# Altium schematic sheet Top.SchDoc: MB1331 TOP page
size A3; Date: Not used; ApprovedBy: Not used; CheckedBy: Not used; Author: Not used; CompanyName: STMicroelectronics; DrawnBy: Not used; Engineer: Not used; Organization: Not used; Address1: Not used; Address2: Not used; Address3: Not used; Address4: Not used; DocumentNumber: Not used; Revision: Not used; SheetNumber: 2; SheetTotal: 23
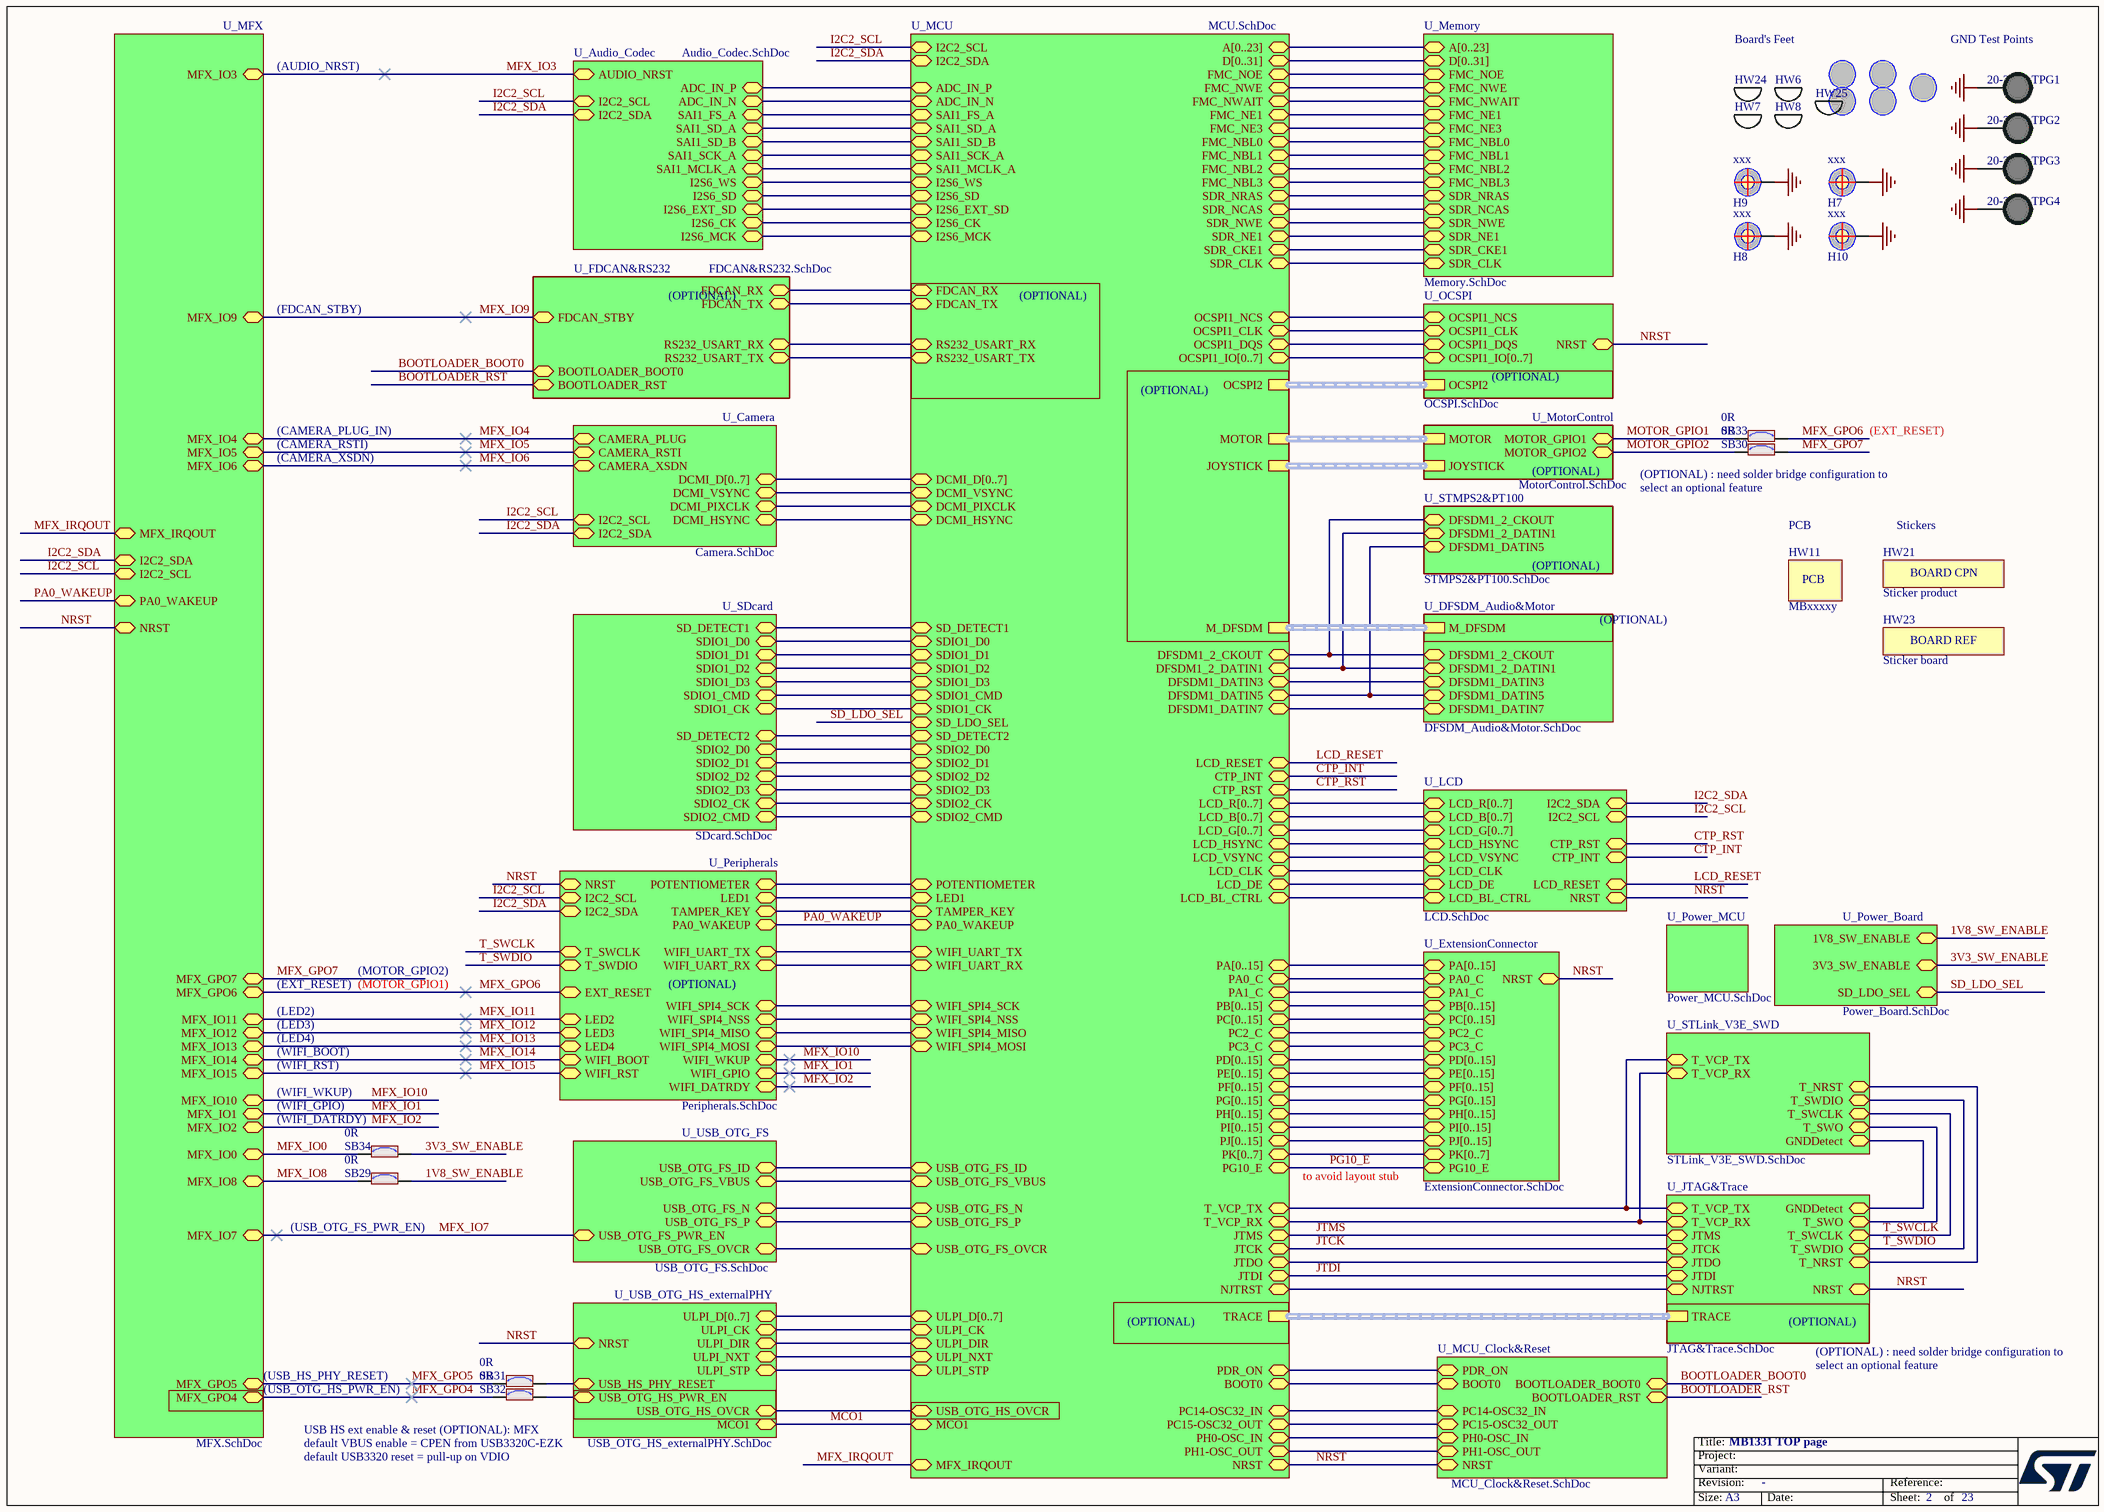
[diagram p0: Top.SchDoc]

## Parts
H7  value xxx  [PTH_M1261-3005-N_3P5X6_M3_H14]  (hidden comment: POSITION HOLE)  (no BOM)
H8  value xxx  [PTH_M1261-3005-N_3P5X6_M3_H14]  (hidden comment: POSITION HOLE)  (no BOM)
H9  value xxx  [PTH_M1261-3005-N_3P5X6_M3_H14]  (hidden comment: POSITION HOLE)  (no BOM)
H10  value xxx  [PTH_M1261-3005-N_3P5X6_M3_H14]  (hidden comment: POSITION HOLE)  (no BOM)
HW6  RUBBER_FOOT  (value not drawn)  (mechanical)
HW7  RUBBER_FOOT  (value not drawn)  (mechanical)
HW8  RUBBER_FOOT  (value not drawn)  (mechanical)
HW11  value MBxxxxy  (hidden comment: PCB)  (no BOM)
HW21  value Sticker product  [STICKER_25X9]  (hidden comment: STICKER_BOARD_CPN)  (no BOM)
HW23  value Sticker board  [STICKER_25X9]  (hidden comment: STICKER_BOARD_REF)  (no BOM)
HW24  RUBBER_FOOT  (value not drawn)  (mechanical)
HW25  RUBBER_FOOT  (value not drawn)  (mechanical)
SB29  value 0R  [SOLDER-BRIDGE_R0603-0R]  (hidden comment: SB_ON)
SB30  value 0R  [SOLDER-BRIDGE_R0603-0R]  (hidden comment: SB_ON)
SB31  value 0R  [SOLDER-BRIDGE_R0603-0R]  (hidden comment: SB_ON)
SB32  value 0R  [SOLDER-BRIDGE_R0603-0R]  (hidden comment: SB_ON)
SB33  value 0R  [SOLDER-BRIDGE_R0603-0R]  (hidden comment: SB_ON)
SB34  value 0R  [SOLDER-BRIDGE_R0603-0R]  (hidden comment: SB_ON)
TPG1  value 20-2137  [TP_PTH-1P02MM_TEST-TERMINAL_RS_101-2391_BLACK]  (hidden comment: Test_pin_conn_black)
TPG2  value 20-2137  [TP_PTH-1P02MM_TEST-TERMINAL_RS_101-2391_BLACK]  (hidden comment: Test_pin_conn_black)
TPG3  value 20-2137  [TP_PTH-1P02MM_TEST-TERMINAL_RS_101-2391_BLACK]  (hidden comment: Test_pin_conn_black)
TPG4  value 20-2137  [TP_PTH-1P02MM_TEST-TERMINAL_RS_101-2391_BLACK]  (hidden comment: Test_pin_conn_black)

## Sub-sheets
U_Audio_Codec = Audio_Codec.SchDoc: AUDIO_NRST (bidir), SAI1_SD_A (bidir), SAI1_SD_B (bidir), I2C2_SCL (bidir), I2C2_SDA (bidir), I2S6_WS (bidir), I2S6_EXT_SD (bidir), SAI1_FS_A (bidir), SAI1_SCK_A (bidir), SAI1_MCLK_A (bidir), ADC_IN_N (bidir), ADC_IN_P (bidir), I2S6_MCK (bidir), I2S6_CK (bidir), I2S6_SD (bidir)
U_Camera = Camera.SchDoc: CAMERA_RSTI (bidir), CAMERA_XSDN (bidir), DCMI_D[0..7] (bidir), CAMERA_PLUG (bidir), DCMI_HSYNC (bidir), DCMI_PIXCLK (bidir), DCMI_VSYNC (bidir), I2C2_SCL (bidir), I2C2_SDA (bidir)
U_DFSDM_Audio&Motor = DFSDM_Audio&Motor.SchDoc: DFSDM1_DATIN7 (bidir), DFSDM1_2_CKOUT (bidir), DFSDM1_2_DATIN1 (bidir), DFSDM1_DATIN3 (bidir), DFSDM1_DATIN5 (bidir), M_DFSDM (harness M_DFSDM)
U_ExtensionConnector = ExtensionConnector.SchDoc: PA[0..15] (bidir), PB[0..15] (bidir), PC[0..15] (bidir), PD[0..15] (bidir), PE[0..15] (bidir), PF[0..15] (bidir), PG[0..15] (bidir), PH[0..15] (bidir), PI[0..15] (bidir), PJ[0..15] (bidir), PK[0..7] (bidir), NRST (bidir), PA0_C (bidir), PA1_C (bidir), PC2_C (bidir), PC3_C (bidir), PG10_E (bidir)
U_FDCAN&RS232 = FDCAN&RS232.SchDoc: RS232_USART_TX (bidir), RS232_USART_RX (bidir), BOOTLOADER_BOOT0 (bidir), BOOTLOADER_RST (bidir), FDCAN_RX (bidir), FDCAN_TX (bidir), FDCAN_STBY (bidir)
U_JTAG&Trace = JTAG&Trace.SchDoc: JTMS (bidir), JTCK (bidir), JTDI (bidir), JTDO (bidir), NJTRST (bidir), NRST (bidir), TRACE (harness TRACE), T_VCP_TX (bidir), T_VCP_RX (bidir), GNDDetect (bidir), T_SWCLK (bidir), T_SWO (bidir), T_SWDIO (bidir), T_NRST (bidir)
U_LCD = LCD.SchDoc: LCD_R[0..7] (bidir), I2C2_SDA (bidir), I2C2_SCL (bidir), LCD_B[0..7] (bidir), LCD_G[0..7] (bidir), NRST (bidir), LCD_HSYNC (bidir), LCD_VSYNC (bidir), LCD_CLK (bidir), LCD_DE (bidir), CTP_INT (bidir), LCD_BL_CTRL (bidir), CTP_RST (bidir), LCD_RESET (bidir)
U_MCU = MCU.SchDoc: OCSPI1_NCS (bidir), SDR_CLK (bidir), FMC_NE3 (bidir), SDR_NCAS (bidir), SDR_NWE (bidir), SDR_NE1 (bidir), SDR_CKE1 (bidir), PH0-OSC_IN (bidir), NRST (bidir), BOOT0 (bidir), PDR_ON (bidir), FMC_NBL2 (bidir), FMC_NBL3 (bidir), LCD_HSYNC (bidir), LCD_VSYNC (bidir), LCD_CLK (bidir), PA0_WAKEUP (bidir), MCO1 (bidir), USB_OTG_FS_VBUS (bidir), USB_OTG_FS_ID (bidir), USB_OTG_FS_N (bidir), USB_OTG_FS_P (bidir), OCSPI1_CLK (bidir), T_VCP_TX (bidir), T_VCP_RX (bidir), OCSPI1_DQS (bidir), SDIO1_D0 (bidir), SDIO1_D1 (bidir), SDIO1_D2 (bidir), SDIO1_D3 (bidir), SDIO1_CK (bidir), TAMPER_KEY (bidir), PC14-OSC32_IN (bidir), PC15-OSC32_OUT (bidir), SDIO1_CMD (bidir), FMC_NOE (bidir), FMC_NWE (bidir), FMC_NWAIT (bidir), FMC_NE1 (bidir), FMC_NBL0 (bidir), FMC_NBL1 (bidir), SDR_NRAS (bidir), DFSDM1_DATIN7 (bidir), DFSDM1_2_CKOUT (bidir), DCMI_HSYNC (bidir), DCMI_PIXCLK (bidir), DCMI_VSYNC (bidir), FDCAN_RX (bidir), FDCAN_TX (bidir), PA[0..15] (bidir), PB[0..15] (bidir), PC[0..15] (bidir), PD[0..15] (bidir), PE[0..15] (bidir), PF[0..15] (bidir), PG[0..15] (bidir), PH[0..15] (bidir), PI[0..15] (bidir), PJ[0..15] (bidir), PK[0..7] (bidir), LCD_G[0..7] (bidir), LCD_B[0..7] (bidir), D[0..31] (bidir), A[0..23] (bidir), ULPI_D[0..7] (bidir), LCD_R[0..7] (bidir), LCD_DE (bidir), DFSDM1_2_DATIN1 (bidir), I2C2_SCL (bidir), I2C2_SDA (bidir), DCMI_D[0..7] (bidir), POTENTIOMETER (bidir), ULPI_NXT (bidir), ULPI_DIR (bidir), ULPI_STP (bidir), ULPI_CK (bidir), CTP_INT (bidir), CTP_RST (bidir), LCD_BL_CTRL (bidir), OCSPI1_IO[0..7] (bidir), PA0_C (bidir), PA1_C (bidir), PC2_C (bidir), PC3_C (bidir), JTMS (bidir), JTCK (bidir), JTDI (bidir), JTDO (bidir), NJTRST (bidir), DFSDM1_DATIN3 (bidir), DFSDM1_DATIN5 (bidir), LCD_RESET (bidir), MFX_IRQOUT (bidir), RS232_USART_TX (bidir), RS232_USART_RX (bidir), SDIO2_CK (bidir), SDIO2_D2 (bidir), SDIO2_D1 (bidir), SDIO2_D3 (bidir), SDIO2_D0 (bidir), SDIO2_CMD (bidir), JOYSTICK (harness JOYSTICK), MOTOR (harness MOTOR), OCSPI2 (harness OCSPI2), TRACE (harness TRACE), M_DFSDM (harness M_DFSDM), PH1-OSC_OUT (bidir), WIFI_SPI4_SCK (bidir), WIFI_SPI4_NSS (bidir), WIFI_SPI4_MISO (bidir), WIFI_SPI4_MOSI (bidir), USB_OTG_FS_OVCR (bidir), LED1 (bidir), ADC_IN_N (bidir), ADC_IN_P (bidir), USB_OTG_HS_OVCR (bidir), SD_DETECT1 (bidir), SD_DETECT2 (bidir), SD_LDO_SEL (bidir), SAI1_SD_A (bidir), SAI1_SD_B (bidir), I2S6_WS (bidir), I2S6_EXT_SD (bidir), SAI1_FS_A (bidir), SAI1_SCK_A (bidir), SAI1_MCLK_A (bidir), I2S6_MCK (bidir), I2S6_CK (bidir), I2S6_SD (bidir), PG10_E (bidir), WIFI_UART_TX (bidir), WIFI_UART_RX (bidir)
U_MCU_Clock&Reset = MCU_Clock&Reset.SchDoc: BOOTLOADER_BOOT0 (bidir), BOOTLOADER_RST (bidir), NRST (bidir), BOOT0 (bidir), PDR_ON (bidir), PH0-OSC_IN (bidir), PC14-OSC32_IN (bidir), PC15-OSC32_OUT (bidir), PH1-OSC_OUT (bidir)
U_Memory = Memory.SchDoc: FMC_NE1 (bidir), FMC_NWE (bidir), FMC_NOE (bidir), FMC_NWAIT (bidir), FMC_NBL0 (bidir), FMC_NBL1 (bidir), D[0..31] (bidir), A[0..23] (bidir), SDR_NCAS (bidir), SDR_NWE (bidir), SDR_NRAS (bidir), SDR_NE1 (bidir), SDR_CKE1 (bidir), SDR_CLK (bidir), FMC_NBL3 (bidir), FMC_NBL2 (bidir), FMC_NE3 (bidir)
U_MFX = MFX.SchDoc: MFX_IRQOUT (bidir), I2C2_SDA (bidir), I2C2_SCL (bidir), PA0_WAKEUP (bidir), NRST (bidir), MFX_IO9 (bidir), MFX_IO4 (bidir), MFX_IO5 (bidir), MFX_IO6 (bidir), MFX_IO8 (bidir), MFX_IO3 (bidir), MFX_IO7 (bidir), MFX_IO14 (bidir), MFX_IO15 (bidir), MFX_IO12 (bidir), MFX_IO11 (bidir), MFX_IO13 (bidir), MFX_GPO5 (bidir), MFX_GPO4 (bidir), MFX_IO0 (bidir), MFX_GPO6 (bidir), MFX_GPO7 (bidir), MFX_IO1 (bidir), MFX_IO2 (bidir), MFX_IO10 (bidir)
U_MotorControl = MotorControl.SchDoc: MOTOR (harness MOTOR), JOYSTICK (harness JOYSTICK), MOTOR_GPIO1 (bidir), MOTOR_GPIO2 (bidir)
U_OCSPI = OCSPI.SchDoc: NRST (bidir), OCSPI1_NCS (bidir), OCSPI1_DQS (bidir), OCSPI1_CLK (bidir), OCSPI1_IO[0..7] (bidir), OCSPI2 (harness OCSPI2)
U_Peripherals = Peripherals.SchDoc: POTENTIOMETER (bidir), LED1 (bidir), LED2 (bidir), LED3 (bidir), LED4 (bidir), WIFI_UART_RX (bidir), WIFI_UART_TX (bidir), WIFI_RST (bidir), EXT_RESET (bidir), TAMPER_KEY (bidir), NRST (bidir), PA0_WAKEUP (bidir), I2C2_SCL (bidir), I2C2_SDA (bidir), WIFI_BOOT (bidir), WIFI_SPI4_SCK (bidir), WIFI_SPI4_NSS (bidir), WIFI_SPI4_MISO (bidir), WIFI_SPI4_MOSI (bidir), T_SWCLK (bidir), T_SWDIO (bidir), WIFI_WKUP (bidir), WIFI_GPIO (bidir), WIFI_DATRDY (bidir)
U_Power_Board = Power_Board.SchDoc: 1V8_SW_ENABLE (bidir), 3V3_SW_ENABLE (bidir), SD_LDO_SEL (bidir)
U_Power_MCU = Power_MCU.SchDoc: no entries
U_SDcard = SDcard.SchDoc: SDIO1_D0 (bidir), SDIO1_D1 (bidir), SDIO1_D2 (bidir), SDIO1_D3 (bidir), SDIO1_CMD (bidir), SD_DETECT2 (bidir), SDIO1_CK (bidir), SDIO2_CK (bidir), SDIO2_D2 (bidir), SDIO2_D1 (bidir), SDIO2_D3 (bidir), SDIO2_D0 (bidir), SDIO2_CMD (bidir), SD_DETECT1 (bidir)
U_STLink_V3E_SWD = STLink_V3E_SWD.SchDoc: T_SWCLK (bidir), T_SWO (bidir), T_SWDIO (bidir), T_VCP_TX (bidir), T_VCP_RX (bidir), GNDDetect (bidir), T_NRST (bidir)
U_STMPS2&PT100 = STMPS2&PT100.SchDoc: DFSDM1_2_CKOUT (bidir), DFSDM1_2_DATIN1 (bidir), DFSDM1_DATIN5 (bidir)
U_USB_OTG_FS = USB_OTG_FS.SchDoc: USB_OTG_FS_VBUS (bidir), USB_OTG_FS_N (bidir), USB_OTG_FS_P (bidir), USB_OTG_FS_ID (bidir), USB_OTG_FS_PWR_EN (bidir), USB_OTG_FS_OVCR (bidir)
U_USB_OTG_HS_externalPHY = USB_OTG_HS_externalPHY.SchDoc: ULPI_D[0..7] (bidir), ULPI_CK (bidir), ULPI_DIR (bidir), ULPI_NXT (bidir), ULPI_STP (bidir), USB_HS_PHY_RESET (bidir), NRST (bidir), USB_OTG_HS_PWR_EN (bidir), USB_OTG_HS_OVCR (bidir), MCO1 (bidir)

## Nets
GND: H7.1 H8.1 H9.1 H10.1 TPG1.1 TPG2.1 TPG3.1 TPG4.1
1V8_SW_ENABLE: SB29.1 ; sheet U_Power_Board/1V8_SW_ENABLE
3V3_SW_ENABLE: SB34.1 ; sheet U_Power_Board/3V3_SW_ENABLE
BOOTLOADER_BOOT0: sheet U_MCU_Clock&Reset/BOOTLOADER_BOOT0, sheet U_FDCAN&RS232/BOOTLOADER_BOOT0
BOOTLOADER_RST: sheet U_MCU_Clock&Reset/BOOTLOADER_RST, sheet U_FDCAN&RS232/BOOTLOADER_RST
CTP_INT: sheet U_MCU/CTP_INT, sheet U_LCD/CTP_INT
CTP_RST: sheet U_MCU/CTP_RST, sheet U_LCD/CTP_RST
I2C2_SCL: sheet U_Camera/I2C2_SCL, sheet U_MCU/I2C2_SCL, sheet U_Audio_Codec/I2C2_SCL, sheet U_LCD/I2C2_SCL, sheet U_MFX/I2C2_SCL, sheet U_Peripherals/I2C2_SCL
I2C2_SDA: sheet U_Camera/I2C2_SDA, sheet U_MCU/I2C2_SDA, sheet U_Audio_Codec/I2C2_SDA, sheet U_LCD/I2C2_SDA, sheet U_MFX/I2C2_SDA, sheet U_Peripherals/I2C2_SDA
JTCK: sheet U_MCU/JTCK, sheet U_JTAG&Trace/JTCK
JTDI: sheet U_MCU/JTDI, sheet U_JTAG&Trace/JTDI
JTMS: sheet U_MCU/JTMS, sheet U_JTAG&Trace/JTMS
LCD_RESET: sheet U_MCU/LCD_RESET, sheet U_LCD/LCD_RESET
MCO1: sheet U_MCU/MCO1, sheet U_USB_OTG_HS_externalPHY/MCO1
MFX_GPO4: SB32.2 ; sheet U_MFX/MFX_GPO4
MFX_GPO5: SB31.2 ; sheet U_MFX/MFX_GPO5
MFX_GPO6: SB33.1 ; sheet U_MFX/MFX_GPO6, sheet U_Peripherals/EXT_RESET
MFX_GPO7: SB30.1 ; sheet U_MFX/MFX_GPO7
MFX_IO0: SB34.2 ; sheet U_MFX/MFX_IO0
MFX_IO1: sheet U_MFX/MFX_IO1, sheet U_Peripherals/WIFI_GPIO
MFX_IO2: sheet U_MFX/MFX_IO2, sheet U_Peripherals/WIFI_DATRDY
MFX_IO3: sheet U_Audio_Codec/AUDIO_NRST, sheet U_MFX/MFX_IO3
MFX_IO4: sheet U_Camera/CAMERA_PLUG, sheet U_MFX/MFX_IO4
MFX_IO5: sheet U_Camera/CAMERA_RSTI, sheet U_MFX/MFX_IO5
MFX_IO6: sheet U_Camera/CAMERA_XSDN, sheet U_MFX/MFX_IO6
MFX_IO7: sheet U_MFX/MFX_IO7, sheet U_USB_OTG_FS/USB_OTG_FS_PWR_EN
MFX_IO8: SB29.2 ; sheet U_MFX/MFX_IO8
MFX_IO9: sheet U_MFX/MFX_IO9, sheet U_FDCAN&RS232/FDCAN_STBY
MFX_IO10: sheet U_MFX/MFX_IO10, sheet U_Peripherals/WIFI_WKUP
MFX_IO11: sheet U_MFX/MFX_IO11, sheet U_Peripherals/LED2
MFX_IO12: sheet U_MFX/MFX_IO12, sheet U_Peripherals/LED3
MFX_IO13: sheet U_MFX/MFX_IO13, sheet U_Peripherals/LED4
MFX_IO14: sheet U_MFX/MFX_IO14, sheet U_Peripherals/WIFI_BOOT
MFX_IO15: sheet U_MFX/MFX_IO15, sheet U_Peripherals/WIFI_RST
MFX_IRQOUT: sheet U_MCU/MFX_IRQOUT, sheet U_MFX/MFX_IRQOUT
MOTOR_GPIO1: SB33.2 ; sheet U_MotorControl/MOTOR_GPIO1
MOTOR_GPIO2: SB30.2 ; sheet U_MotorControl/MOTOR_GPIO2
NRST: sheet U_MCU/NRST, sheet U_LCD/NRST, sheet U_JTAG&Trace/NRST, sheet U_MCU_Clock&Reset/NRST, sheet U_MFX/NRST, sheet U_OCSPI/NRST, sheet U_Peripherals/NRST, sheet U_ExtensionConnector/NRST, sheet U_USB_OTG_HS_externalPHY/NRST
PA0_WAKEUP: sheet U_MCU/PA0_WAKEUP, sheet U_MFX/PA0_WAKEUP, sheet U_Peripherals/PA0_WAKEUP
PG10_E: sheet U_MCU/PG10_E, sheet U_ExtensionConnector/PG10_E
SD_LDO_SEL: sheet U_MCU/SD_LDO_SEL, sheet U_Power_Board/SD_LDO_SEL
T_SWCLK: sheet U_JTAG&Trace/T_SWCLK, sheet U_Peripherals/T_SWCLK, sheet U_STLink_V3E_SWD/T_SWCLK
T_SWDIO: sheet U_JTAG&Trace/T_SWDIO, sheet U_Peripherals/T_SWDIO, sheet U_STLink_V3E_SWD/T_SWDIO
NetSB31_1: SB31.1 ; sheet U_USB_OTG_HS_externalPHY/USB_HS_PHY_RESET
NetSB32_1: SB32.1 ; sheet U_USB_OTG_HS_externalPHY/USB_OTG_HS_PWR_EN
(unnamed): sheet U_SDcard/SDIO1_D0, sheet U_MCU/SDIO1_D0
(unnamed): sheet U_SDcard/SDIO1_D1, sheet U_MCU/SDIO1_D1  [a separate net that carries the same name]
(unnamed): sheet U_SDcard/SDIO1_D2, sheet U_MCU/SDIO1_D2  [a separate net that carries the same name]
(unnamed): sheet U_SDcard/SDIO1_D3, sheet U_MCU/SDIO1_D3  [a separate net that carries the same name]
(unnamed): sheet U_SDcard/SDIO1_CMD, sheet U_MCU/SDIO1_CMD  [a separate net that carries the same name]
(unnamed): sheet U_SDcard/SD_DETECT2, sheet U_MCU/SD_DETECT2  [a separate net that carries the same name]
(unnamed): sheet U_SDcard/SDIO1_CK, sheet U_MCU/SDIO1_CK  [a separate net that carries the same name]
(unnamed): sheet U_SDcard/SDIO2_CK, sheet U_MCU/SDIO2_CK  [a separate net that carries the same name]
(unnamed): sheet U_SDcard/SDIO2_D2, sheet U_MCU/SDIO2_D2  [a separate net that carries the same name]
(unnamed): sheet U_SDcard/SDIO2_D1, sheet U_MCU/SDIO2_D1  [a separate net that carries the same name]
(unnamed): sheet U_SDcard/SDIO2_D3, sheet U_MCU/SDIO2_D3  [a separate net that carries the same name]
(unnamed): sheet U_SDcard/SDIO2_D0, sheet U_MCU/SDIO2_D0  [a separate net that carries the same name]
(unnamed): sheet U_SDcard/SDIO2_CMD, sheet U_MCU/SDIO2_CMD  [a separate net that carries the same name]
(unnamed): sheet U_SDcard/SD_DETECT1, sheet U_MCU/SD_DETECT1  [a separate net that carries the same name]
(unnamed): sheet U_Camera/DCMI_HSYNC, sheet U_MCU/DCMI_HSYNC  [a separate net that carries the same name]
(unnamed): sheet U_Camera/DCMI_PIXCLK, sheet U_MCU/DCMI_PIXCLK  [a separate net that carries the same name]
(unnamed): sheet U_Camera/DCMI_VSYNC, sheet U_MCU/DCMI_VSYNC  [a separate net that carries the same name]
(unnamed): sheet U_MCU/OCSPI1_NCS, sheet U_OCSPI/OCSPI1_NCS  [a separate net that carries the same name]
(unnamed): sheet U_MCU/SDR_CLK, sheet U_Memory/SDR_CLK  [a separate net that carries the same name]
(unnamed): sheet U_MCU/FMC_NE3, sheet U_Memory/FMC_NE3  [a separate net that carries the same name]
(unnamed): sheet U_MCU/SDR_NCAS, sheet U_Memory/SDR_NCAS  [a separate net that carries the same name]
(unnamed): sheet U_MCU/SDR_NWE, sheet U_Memory/SDR_NWE  [a separate net that carries the same name]
(unnamed): sheet U_MCU/SDR_NE1, sheet U_Memory/SDR_NE1  [a separate net that carries the same name]
(unnamed): sheet U_MCU/SDR_CKE1, sheet U_Memory/SDR_CKE1  [a separate net that carries the same name]
(unnamed): sheet U_MCU/PH0-OSC_IN, sheet U_MCU_Clock&Reset/PH0-OSC_IN  [a separate net that carries the same name]
(unnamed): sheet U_MCU/BOOT0, sheet U_MCU_Clock&Reset/BOOT0  [a separate net that carries the same name]
(unnamed): sheet U_MCU/PDR_ON, sheet U_MCU_Clock&Reset/PDR_ON  [a separate net that carries the same name]
(unnamed): sheet U_MCU/FMC_NBL2, sheet U_Memory/FMC_NBL2  [a separate net that carries the same name]
(unnamed): sheet U_MCU/FMC_NBL3, sheet U_Memory/FMC_NBL3  [a separate net that carries the same name]
(unnamed): sheet U_MCU/LCD_HSYNC, sheet U_LCD/LCD_HSYNC  [a separate net that carries the same name]
(unnamed): sheet U_MCU/LCD_VSYNC, sheet U_LCD/LCD_VSYNC  [a separate net that carries the same name]
(unnamed): sheet U_MCU/LCD_CLK, sheet U_LCD/LCD_CLK  [a separate net that carries the same name]
(unnamed): sheet U_MCU/USB_OTG_FS_VBUS, sheet U_USB_OTG_FS/USB_OTG_FS_VBUS  [a separate net that carries the same name]
(unnamed): sheet U_MCU/USB_OTG_FS_ID, sheet U_USB_OTG_FS/USB_OTG_FS_ID  [a separate net that carries the same name]
(unnamed): sheet U_MCU/USB_OTG_FS_N, sheet U_USB_OTG_FS/USB_OTG_FS_N  [a separate net that carries the same name]
(unnamed): sheet U_MCU/USB_OTG_FS_P, sheet U_USB_OTG_FS/USB_OTG_FS_P  [a separate net that carries the same name]
(unnamed): sheet U_MCU/OCSPI1_CLK, sheet U_OCSPI/OCSPI1_CLK  [a separate net that carries the same name]
(unnamed): sheet U_MCU/T_VCP_TX, sheet U_JTAG&Trace/T_VCP_TX, sheet U_STLink_V3E_SWD/T_VCP_TX  [a separate net that carries the same name]
(unnamed): sheet U_MCU/T_VCP_RX, sheet U_JTAG&Trace/T_VCP_RX, sheet U_STLink_V3E_SWD/T_VCP_RX  [a separate net that carries the same name]
(unnamed): sheet U_MCU/OCSPI1_DQS, sheet U_OCSPI/OCSPI1_DQS  [a separate net that carries the same name]
(unnamed): sheet U_MCU/TAMPER_KEY, sheet U_Peripherals/TAMPER_KEY  [a separate net that carries the same name]
(unnamed): sheet U_MCU/PC14-OSC32_IN, sheet U_MCU_Clock&Reset/PC14-OSC32_IN  [a separate net that carries the same name]
(unnamed): sheet U_MCU/PC15-OSC32_OUT, sheet U_MCU_Clock&Reset/PC15-OSC32_OUT  [a separate net that carries the same name]
(unnamed): sheet U_MCU/FMC_NOE, sheet U_Memory/FMC_NOE  [a separate net that carries the same name]
(unnamed): sheet U_MCU/FMC_NWE, sheet U_Memory/FMC_NWE  [a separate net that carries the same name]
(unnamed): sheet U_MCU/FMC_NWAIT, sheet U_Memory/FMC_NWAIT  [a separate net that carries the same name]
(unnamed): sheet U_MCU/FMC_NE1, sheet U_Memory/FMC_NE1  [a separate net that carries the same name]
(unnamed): sheet U_MCU/FMC_NBL0, sheet U_Memory/FMC_NBL0  [a separate net that carries the same name]
(unnamed): sheet U_MCU/FMC_NBL1, sheet U_Memory/FMC_NBL1  [a separate net that carries the same name]
(unnamed): sheet U_MCU/SDR_NRAS, sheet U_Memory/SDR_NRAS  [a separate net that carries the same name]
(unnamed): sheet U_MCU/DFSDM1_DATIN7, sheet U_DFSDM_Audio&Motor/DFSDM1_DATIN7  [a separate net that carries the same name]
(unnamed): sheet U_MCU/DFSDM1_2_CKOUT, sheet U_DFSDM_Audio&Motor/DFSDM1_2_CKOUT, sheet U_STMPS2&PT100/DFSDM1_2_CKOUT  [a separate net that carries the same name]
(unnamed): sheet U_MCU/FDCAN_RX, sheet U_FDCAN&RS232/FDCAN_RX  [a separate net that carries the same name]
(unnamed): sheet U_MCU/FDCAN_TX, sheet U_FDCAN&RS232/FDCAN_TX  [a separate net that carries the same name]
(unnamed): sheet U_MCU/LCD_DE, sheet U_LCD/LCD_DE  [a separate net that carries the same name]
(unnamed): sheet U_MCU/DFSDM1_2_DATIN1, sheet U_DFSDM_Audio&Motor/DFSDM1_2_DATIN1, sheet U_STMPS2&PT100/DFSDM1_2_DATIN1  [a separate net that carries the same name]
(unnamed): sheet U_MCU/POTENTIOMETER, sheet U_Peripherals/POTENTIOMETER  [a separate net that carries the same name]
(unnamed): sheet U_MCU/ULPI_NXT, sheet U_USB_OTG_HS_externalPHY/ULPI_NXT  [a separate net that carries the same name]
(unnamed): sheet U_MCU/ULPI_DIR, sheet U_USB_OTG_HS_externalPHY/ULPI_DIR  [a separate net that carries the same name]
(unnamed): sheet U_MCU/ULPI_STP, sheet U_USB_OTG_HS_externalPHY/ULPI_STP  [a separate net that carries the same name]
(unnamed): sheet U_MCU/ULPI_CK, sheet U_USB_OTG_HS_externalPHY/ULPI_CK  [a separate net that carries the same name]
(unnamed): sheet U_MCU/LCD_BL_CTRL, sheet U_LCD/LCD_BL_CTRL  [a separate net that carries the same name]
(unnamed): sheet U_MCU/PA0_C, sheet U_ExtensionConnector/PA0_C  [a separate net that carries the same name]
(unnamed): sheet U_MCU/PA1_C, sheet U_ExtensionConnector/PA1_C  [a separate net that carries the same name]
(unnamed): sheet U_MCU/PC2_C, sheet U_ExtensionConnector/PC2_C  [a separate net that carries the same name]
(unnamed): sheet U_MCU/PC3_C, sheet U_ExtensionConnector/PC3_C  [a separate net that carries the same name]
(unnamed): sheet U_MCU/JTDO, sheet U_JTAG&Trace/JTDO  [a separate net that carries the same name]
(unnamed): sheet U_MCU/NJTRST, sheet U_JTAG&Trace/NJTRST  [a separate net that carries the same name]
(unnamed): sheet U_MCU/DFSDM1_DATIN3, sheet U_DFSDM_Audio&Motor/DFSDM1_DATIN3  [a separate net that carries the same name]
(unnamed): sheet U_MCU/DFSDM1_DATIN5, sheet U_DFSDM_Audio&Motor/DFSDM1_DATIN5, sheet U_STMPS2&PT100/DFSDM1_DATIN5  [a separate net that carries the same name]
(unnamed): sheet U_MCU/RS232_USART_TX, sheet U_FDCAN&RS232/RS232_USART_TX  [a separate net that carries the same name]
(unnamed): sheet U_MCU/RS232_USART_RX, sheet U_FDCAN&RS232/RS232_USART_RX  [a separate net that carries the same name]
(unnamed): sheet U_MCU/PH1-OSC_OUT, sheet U_MCU_Clock&Reset/PH1-OSC_OUT  [a separate net that carries the same name]
(unnamed): sheet U_MCU/WIFI_SPI4_SCK, sheet U_Peripherals/WIFI_SPI4_SCK  [a separate net that carries the same name]
(unnamed): sheet U_MCU/WIFI_SPI4_NSS, sheet U_Peripherals/WIFI_SPI4_NSS  [a separate net that carries the same name]
(unnamed): sheet U_MCU/WIFI_SPI4_MISO, sheet U_Peripherals/WIFI_SPI4_MISO  [a separate net that carries the same name]
(unnamed): sheet U_MCU/WIFI_SPI4_MOSI, sheet U_Peripherals/WIFI_SPI4_MOSI  [a separate net that carries the same name]
(unnamed): sheet U_MCU/USB_OTG_FS_OVCR, sheet U_USB_OTG_FS/USB_OTG_FS_OVCR  [a separate net that carries the same name]
(unnamed): sheet U_MCU/LED1, sheet U_Peripherals/LED1  [a separate net that carries the same name]
(unnamed): sheet U_MCU/ADC_IN_N, sheet U_Audio_Codec/ADC_IN_N  [a separate net that carries the same name]
(unnamed): sheet U_MCU/ADC_IN_P, sheet U_Audio_Codec/ADC_IN_P  [a separate net that carries the same name]
(unnamed): sheet U_MCU/USB_OTG_HS_OVCR, sheet U_USB_OTG_HS_externalPHY/USB_OTG_HS_OVCR  [a separate net that carries the same name]
(unnamed): sheet U_MCU/SAI1_SD_A, sheet U_Audio_Codec/SAI1_SD_A  [a separate net that carries the same name]
(unnamed): sheet U_MCU/SAI1_SD_B, sheet U_Audio_Codec/SAI1_SD_B  [a separate net that carries the same name]
(unnamed): sheet U_MCU/I2S6_WS, sheet U_Audio_Codec/I2S6_WS  [a separate net that carries the same name]
(unnamed): sheet U_MCU/I2S6_EXT_SD, sheet U_Audio_Codec/I2S6_EXT_SD  [a separate net that carries the same name]
(unnamed): sheet U_MCU/SAI1_FS_A, sheet U_Audio_Codec/SAI1_FS_A  [a separate net that carries the same name]
(unnamed): sheet U_MCU/SAI1_SCK_A, sheet U_Audio_Codec/SAI1_SCK_A  [a separate net that carries the same name]
(unnamed): sheet U_MCU/SAI1_MCLK_A, sheet U_Audio_Codec/SAI1_MCLK_A  [a separate net that carries the same name]
(unnamed): sheet U_MCU/I2S6_MCK, sheet U_Audio_Codec/I2S6_MCK  [a separate net that carries the same name]
(unnamed): sheet U_MCU/I2S6_CK, sheet U_Audio_Codec/I2S6_CK  [a separate net that carries the same name]
(unnamed): sheet U_MCU/I2S6_SD, sheet U_Audio_Codec/I2S6_SD  [a separate net that carries the same name]
(unnamed): sheet U_MCU/WIFI_UART_TX, sheet U_Peripherals/WIFI_UART_TX  [a separate net that carries the same name]
(unnamed): sheet U_MCU/WIFI_UART_RX, sheet U_Peripherals/WIFI_UART_RX  [a separate net that carries the same name]
(unnamed): sheet U_JTAG&Trace/GNDDetect, sheet U_STLink_V3E_SWD/GNDDetect  [a separate net that carries the same name]
(unnamed): sheet U_JTAG&Trace/T_SWO, sheet U_STLink_V3E_SWD/T_SWO  [a separate net that carries the same name]
(unnamed): sheet U_JTAG&Trace/T_NRST, sheet U_STLink_V3E_SWD/T_NRST  [a separate net that carries the same name]

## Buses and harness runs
bus sheet U_Camera/DCMI_D[0..7] = sheet U_MCU/DCMI_D[0..7]
bus sheet U_ExtensionConnector/PA[0..15] = sheet U_MCU/PA[0..15]
bus sheet U_ExtensionConnector/PB[0..15] = sheet U_MCU/PB[0..15]
bus sheet U_ExtensionConnector/PC[0..15] = sheet U_MCU/PC[0..15]
bus sheet U_ExtensionConnector/PD[0..15] = sheet U_MCU/PD[0..15]
bus sheet U_ExtensionConnector/PE[0..15] = sheet U_MCU/PE[0..15]
bus sheet U_ExtensionConnector/PF[0..15] = sheet U_MCU/PF[0..15]
bus sheet U_ExtensionConnector/PG[0..15] = sheet U_MCU/PG[0..15]
bus sheet U_ExtensionConnector/PH[0..15] = sheet U_MCU/PH[0..15]
bus sheet U_ExtensionConnector/PI[0..15] = sheet U_MCU/PI[0..15]
bus sheet U_ExtensionConnector/PJ[0..15] = sheet U_MCU/PJ[0..15]
bus sheet U_ExtensionConnector/PK[0..7] = sheet U_MCU/PK[0..7]
bus sheet U_LCD/LCD_B[0..7] = sheet U_MCU/LCD_B[0..7]
bus sheet U_LCD/LCD_G[0..7] = sheet U_MCU/LCD_G[0..7]
bus sheet U_LCD/LCD_R[0..7] = sheet U_MCU/LCD_R[0..7]
bus sheet U_MCU/A[0..23] = sheet U_Memory/A[0..23]
bus sheet U_MCU/D[0..31] = sheet U_Memory/D[0..31]
bus sheet U_MCU/OCSPI1_IO[0..7] = sheet U_OCSPI/OCSPI1_IO[0..7]
bus sheet U_MCU/ULPI_D[0..7] = sheet U_USB_OTG_HS_externalPHY/ULPI_D[0..7]
harness sheet U_DFSDM_Audio&Motor/M_DFSDM = sheet U_MCU/M_DFSDM
harness sheet U_JTAG&Trace/TRACE = sheet U_MCU/TRACE
harness sheet U_MCU/JOYSTICK = sheet U_MotorControl/JOYSTICK
harness sheet U_MCU/MOTOR = sheet U_MotorControl/MOTOR
harness sheet U_MCU/OCSPI2 = sheet U_OCSPI/OCSPI2

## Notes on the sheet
- Board's Feet
- (near TPG1) GND Test Points
- (AUDIO_NRST)
- (FDCAN_STBY)
- (OPTIONAL)
- (CAMERA_PLUG_IN)
- (CAMERA_RSTI)
- (EXT_RESET)
- (CAMERA_XSDN)
- (near SB30) (OPTIONAL) : need solder bridge configuration to select an optional feature
- (near HW11) PCB
- (near HW21) Stickers
- (MOTOR_GPIO1)
- (MOTOR_GPIO2)
- (WIFI_BOOT)
- (LED2)
- (LED3)
- (LED4)
- (WIFI_RST)
- (WIFI_GPIO)
- (near SB34) (WIFI_DATRDY)
- (WIFI_WKUP)
- to avoid layout stub
- (near SB29) (USB_OTG_FS_PWR_EN)
- (USB_HS_PHY_RESET)
- (USB_OTG_HS_PWR_EN)
- (OPTIONAL) : need solder bridge configuration to select an optional feature
- default VBUS enable = CPEN from USB3320C-EZK
- default USB3320 reset = pull-up on VDIO
- USB HS ext enable & reset (OPTIONAL): MFX

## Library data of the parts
H7-H10 = MCD-00035: POSITION HOLE C6D3R5; Part_Type: Misc; Part_Preference: Recommended; Component_Country_Of_Origin: Unknown; ID: 2482; ShowFields: YES
HW6-HW8 HW24 HW25 = MCD-01240: Rubber Foot (diameter = 10mm, height = 8mm); Part_Type: Mechanical; Manufacturer: 3M; Part_Preference: Recommended; Value: SJ61A4; Provided_By: SUBCO; Component_Country_Of_Origin: Unknown; ID: 3256; ShowFields: YES
HW11 = MCD-00216: PCB, xxxx for PCB number, Y for PCB revision; Part_Type: Misc; Part_Preference: Forbidden; Provided_By: SUBCO; Component_Country_Of_Origin: Unknown; ID: 2653; ShowFields: YES
HW21 = MCD-00547: Sticker to mention board CPN code; Part_Type: Misc; Part_Preference: Recommended; Provided_By: SUBCO; Component_Country_Of_Origin: Unknown; ID: 3197; ShowFields: YES
HW23 = MCD-00235: Sticker to mention board reference + serial number; Part_Type: Misc; Part_Preference: Recommended; Provided_By: SUBCO; Component_Country_Of_Origin: Unknown; ID: 2632; ShowFields: YES
SB29-SB34 = MCD-00071: Solder Bridge ON; Part_Type: Resistor; Manufacturer_Part_Number: RC0603JR-070RL; Manufacturer: YAGEO; Manufacturer_HQ_COO: Unknown; Part_Preference: Recommended; Provided_By: SUBCO; Component_Country_Of_Origin: China; ID: 2521; Order_Code_RS: 199-5647; ShowFields: YES
TPG1-TPG4 = MCD-00713: Vero Technologies 1.02mm Black Terminal Post; Part_Type: Misc; Part_Preference: Recommended; Order_Code_RS: 101-2391; Provided_By: SUBCO; Component_Country_Of_Origin: UK; ID: 3032; ShowFields: YES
